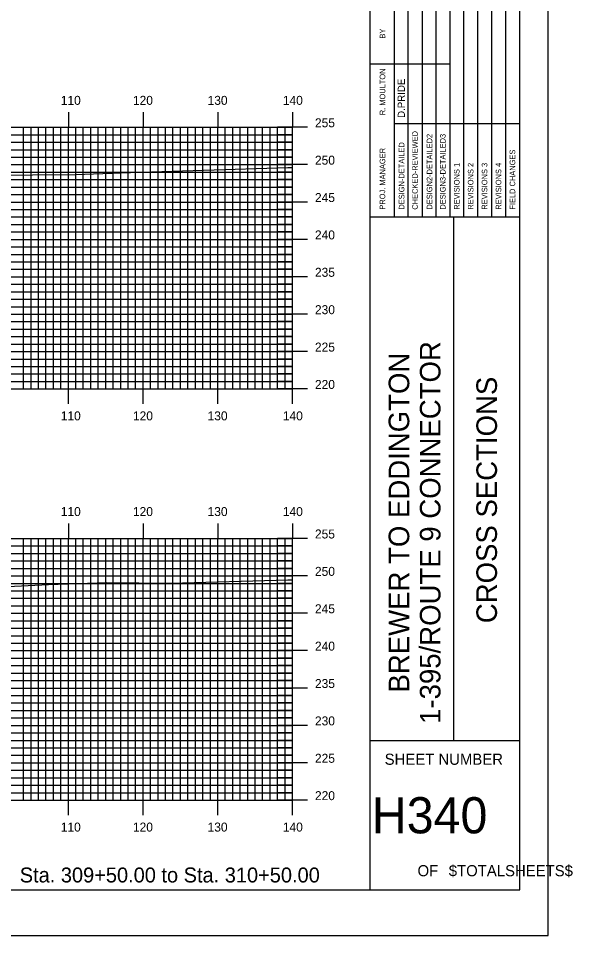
# Model space of a CAD drawing. Extents: x 1818063 to 1818407, y 442591 to 442811.
# Drawn here: x 1818332.4 to 1818406.6, y 442590.5 to 442713.2 of the extents above; entities that cross this region are included whole.
import ezdxf

# ---------------------------------------------------------------- set-up
doc = ezdxf.new("R2010")
doc.units = 0
for name, color, linetype in [('BORDER', 7, 'Continuous'), ('H_V ANNOTATION', 7, 'Continuous'), ('MAJOR', 7, 'Continuous'), ('MINOR', 7, 'Continuous'), ('PLOT BOUNDARY', 7, 'Continuous'), ('S_Roadway_Centerline', 7, 'Continuous')]:
    doc.layers.add(name, color=color, linetype=linetype)

msp = doc.modelspace()

# ---------------------------------------------------------------- linework, layer by layer
at = {"layer": 'BORDER'}
for p, q in [((1818379.53, 442596.67), (1818379.53, 442806.67)), ((1818379.53, 442686.67), (1818399.53, 442686.67)), ((1818390.71, 442616.67), (1818390.71, 442686.67)), ((1818379.53, 442616.67), (1818399.53, 442616.67))]:
    msp.add_line(p, q, dxfattribs=at)
msp.add_lwpolyline([(1818079.53, 442596.67), (1818399.53, 442596.67), (1818399.53, 442806.67), (1818079.53, 442806.67)], close=True, dxfattribs=at)
for points in [[(1818384.62, 442686.68), (1818384.62, 442721.67)], [(1818386.48, 442721.67), (1818386.48, 442686.68)], [(1818388.35, 442686.68), (1818388.35, 442721.67)], [(1818390.21, 442686.68), (1818390.21, 442721.67)], [(1818392.07, 442686.68), (1818392.07, 442721.67)], [(1818393.94, 442686.68), (1818393.94, 442721.67)], [(1818395.8, 442686.68), (1818395.8, 442721.67)], [(1818397.66, 442686.68), (1818397.66, 442721.67)], [(1818382.76, 442686.68), (1818382.76, 442720.26)], [(1818379.53, 442707.17), (1818382.76, 442707.17)], [(1818382.76, 442707.17), (1818390.21, 442707.17)], [(1818382.76, 442699.17), (1818399.53, 442699.17)]]:
    msp.add_lwpolyline(points, dxfattribs=at)
at = {"layer": 'MAJOR'}
for p, q in [((1818339.13, 442700.67), (1818339.13, 442698.67)), ((1818349.13, 442700.67), (1818349.13, 442698.67)), ((1818359.13, 442700.67), (1818359.13, 442698.67)), ((1818369.13, 442700.67), (1818369.13, 442698.67)), ((1818089.13, 442698.67), (1818369.13, 442698.67)), ((1818089.13, 442698.67), (1818369.13, 442698.67)), ((1818339.13, 442663.67), (1818339.13, 442698.67)), ((1818349.13, 442663.67), (1818349.13, 442698.67)), ((1818359.13, 442663.67), (1818359.13, 442698.67)), ((1818371.13, 442698.67), (1818367.12, 442698.67)), ((1818369.13, 442663.67), (1818369.13, 442698.67)), ((1818369.13, 442663.67), (1818369.13, 442698.67)), ((1818089.13, 442693.67), (1818369.13, 442693.67)), ((1818371.13, 442693.67), (1818367.12, 442693.67)), ((1818089.13, 442688.67), (1818369.13, 442688.67)), ((1818371.13, 442688.67), (1818367.12, 442688.67)), ((1818089.13, 442683.67), (1818369.13, 442683.67)), ((1818371.13, 442683.67), (1818367.12, 442683.67)), ((1818089.13, 442678.67), (1818369.13, 442678.67)), ((1818371.13, 442678.67), (1818367.12, 442678.67)), ((1818089.13, 442673.67), (1818369.13, 442673.67)), ((1818371.13, 442673.67), (1818367.12, 442673.67)), ((1818089.13, 442668.67), (1818369.13, 442668.67)), ((1818371.13, 442668.67), (1818367.12, 442668.67)), ((1818089.13, 442663.67), (1818369.13, 442663.67)), ((1818089.13, 442663.67), (1818369.13, 442663.67)), ((1818339.13, 442661.66), (1818339.13, 442663.67)), ((1818349.13, 442661.66), (1818349.13, 442663.67)), ((1818359.13, 442661.66), (1818359.13, 442663.67)), ((1818371.13, 442663.67), (1818367.12, 442663.67)), ((1818369.13, 442661.66), (1818369.13, 442663.67)), ((1818339.13, 442645.67), (1818339.13, 442643.67)), ((1818349.13, 442645.67), (1818349.13, 442643.67)), ((1818359.13, 442645.67), (1818359.13, 442643.67)), ((1818369.13, 442645.67), (1818369.13, 442643.67)), ((1818089.13, 442643.67), (1818369.13, 442643.67)), ((1818089.13, 442643.67), (1818369.13, 442643.67)), ((1818339.13, 442608.67), (1818339.13, 442643.67)), ((1818349.13, 442608.67), (1818349.13, 442643.67)), ((1818359.13, 442608.67), (1818359.13, 442643.67)), ((1818371.13, 442643.67), (1818367.12, 442643.67)), ((1818369.13, 442608.67), (1818369.13, 442643.67)), ((1818369.13, 442608.67), (1818369.13, 442643.67)), ((1818089.13, 442638.67), (1818369.13, 442638.67)), ((1818371.13, 442638.67), (1818367.12, 442638.67)), ((1818089.13, 442633.67), (1818369.13, 442633.67)), ((1818371.13, 442633.67), (1818367.12, 442633.67)), ((1818089.13, 442628.67), (1818369.13, 442628.67)), ((1818371.13, 442628.67), (1818367.12, 442628.67)), ((1818089.13, 442623.67), (1818369.13, 442623.67)), ((1818371.13, 442623.67), (1818367.12, 442623.67)), ((1818089.13, 442618.67), (1818369.13, 442618.67)), ((1818371.13, 442618.67), (1818367.12, 442618.67)), ((1818089.13, 442613.67), (1818369.13, 442613.67)), ((1818371.13, 442613.67), (1818367.12, 442613.67)), ((1818089.13, 442608.67), (1818369.13, 442608.67)), ((1818089.13, 442608.67), (1818369.13, 442608.67)), ((1818339.13, 442606.66), (1818339.13, 442608.67)), ((1818349.13, 442606.66), (1818349.13, 442608.67)), ((1818359.13, 442606.66), (1818359.13, 442608.67)), ((1818371.13, 442608.67), (1818367.12, 442608.67)), ((1818369.13, 442606.66), (1818369.13, 442608.67))]:
    msp.add_line(p, q, dxfattribs=at)
at = {"layer": 'MINOR'}
for p, q in [((1818333.13, 442663.67), (1818333.13, 442698.67)), ((1818334.13, 442663.67), (1818334.13, 442698.67)), ((1818335.13, 442663.67), (1818335.13, 442698.67)), ((1818336.13, 442663.67), (1818336.13, 442698.67)), ((1818337.13, 442663.67), (1818337.13, 442698.67)), ((1818338.13, 442663.67), (1818338.13, 442698.67)), ((1818340.13, 442663.67), (1818340.13, 442698.67)), ((1818341.13, 442663.67), (1818341.13, 442698.67)), ((1818342.13, 442663.67), (1818342.13, 442698.67)), ((1818343.13, 442663.67), (1818343.13, 442698.67)), ((1818344.13, 442663.67), (1818344.13, 442698.67)), ((1818345.13, 442663.67), (1818345.13, 442698.67)), ((1818346.13, 442663.67), (1818346.13, 442698.67)), ((1818347.13, 442663.67), (1818347.13, 442698.67)), ((1818348.13, 442663.67), (1818348.13, 442698.67)), ((1818350.13, 442663.67), (1818350.13, 442698.67)), ((1818351.13, 442663.67), (1818351.13, 442698.67)), ((1818352.13, 442663.67), (1818352.13, 442698.67)), ((1818353.13, 442663.67), (1818353.13, 442698.67)), ((1818354.13, 442663.67), (1818354.13, 442698.67)), ((1818355.13, 442663.67), (1818355.13, 442698.67)), ((1818356.13, 442663.67), (1818356.13, 442698.67)), ((1818357.13, 442663.67), (1818357.13, 442698.67)), ((1818358.13, 442663.67), (1818358.13, 442698.67)), ((1818360.13, 442663.67), (1818360.13, 442698.67)), ((1818361.13, 442663.67), (1818361.13, 442698.67)), ((1818362.13, 442663.67), (1818362.13, 442698.67)), ((1818363.13, 442663.67), (1818363.13, 442698.67)), ((1818364.13, 442663.67), (1818364.13, 442698.67)), ((1818365.13, 442663.67), (1818365.13, 442698.67)), ((1818366.13, 442663.67), (1818366.13, 442698.67)), ((1818367.13, 442663.67), (1818367.13, 442698.67)), ((1818368.13, 442663.67), (1818368.13, 442698.67)), ((1818089.13, 442697.67), (1818369.13, 442697.67)), ((1818089.13, 442696.67), (1818369.13, 442696.67)), ((1818369.13, 442697.67), (1818367.12, 442697.67)), ((1818369.13, 442696.67), (1818367.12, 442696.67)), ((1818089.13, 442695.67), (1818369.13, 442695.67)), ((1818369.13, 442695.67), (1818367.12, 442695.67)), ((1818089.13, 442694.67), (1818369.13, 442694.67)), ((1818369.13, 442694.67), (1818367.12, 442694.67)), ((1818089.13, 442692.67), (1818369.13, 442692.67)), ((1818369.13, 442692.67), (1818367.12, 442692.67)), ((1818089.13, 442691.67), (1818369.13, 442691.67)), ((1818089.13, 442690.67), (1818369.13, 442690.67)), ((1818369.13, 442691.67), (1818367.12, 442691.67)), ((1818369.13, 442690.67), (1818367.12, 442690.67)), ((1818089.13, 442689.67), (1818369.13, 442689.67)), ((1818369.13, 442689.67), (1818367.12, 442689.67)), ((1818089.13, 442687.67), (1818369.13, 442687.67)), ((1818369.13, 442687.67), (1818367.12, 442687.67)), ((1818089.13, 442686.67), (1818369.13, 442686.67)), ((1818089.13, 442685.67), (1818369.13, 442685.67)), ((1818369.13, 442686.67), (1818367.12, 442686.67)), ((1818369.13, 442685.67), (1818367.12, 442685.67)), ((1818089.13, 442684.67), (1818369.13, 442684.67)), ((1818369.13, 442684.67), (1818367.12, 442684.67)), ((1818089.13, 442682.67), (1818369.13, 442682.67)), ((1818369.13, 442682.67), (1818367.12, 442682.67)), ((1818089.13, 442681.67), (1818369.13, 442681.67)), ((1818089.13, 442680.67), (1818369.13, 442680.67)), ((1818369.13, 442681.67), (1818367.12, 442681.67)), ((1818369.13, 442680.67), (1818367.12, 442680.67)), ((1818089.13, 442679.67), (1818369.13, 442679.67)), ((1818369.13, 442679.67), (1818367.12, 442679.67)), ((1818089.13, 442677.67), (1818369.13, 442677.67)), ((1818369.13, 442677.67), (1818367.12, 442677.67)), ((1818089.13, 442676.67), (1818369.13, 442676.67)), ((1818369.13, 442676.67), (1818367.12, 442676.67)), ((1818089.13, 442675.67), (1818369.13, 442675.67)), ((1818089.13, 442674.67), (1818369.13, 442674.67)), ((1818369.13, 442675.67), (1818367.12, 442675.67)), ((1818369.13, 442674.67), (1818367.12, 442674.67)), ((1818089.13, 442672.67), (1818369.13, 442672.67)), ((1818369.13, 442672.67), (1818367.12, 442672.67)), ((1818089.13, 442671.67), (1818369.13, 442671.67)), ((1818369.13, 442671.67), (1818367.12, 442671.67)), ((1818089.13, 442670.67), (1818369.13, 442670.67)), ((1818089.13, 442669.67), (1818369.13, 442669.67)), ((1818369.13, 442670.67), (1818367.12, 442670.67)), ((1818369.13, 442669.67), (1818367.12, 442669.67)), ((1818089.13, 442667.67), (1818369.13, 442667.67)), ((1818369.13, 442667.67), (1818367.12, 442667.67)), ((1818089.13, 442666.67), (1818369.13, 442666.67)), ((1818369.13, 442666.67), (1818367.12, 442666.67)), ((1818089.13, 442665.67), (1818369.13, 442665.67)), ((1818369.13, 442665.67), (1818367.12, 442665.67)), ((1818089.13, 442664.67), (1818369.13, 442664.67)), ((1818369.13, 442664.67), (1818367.12, 442664.67)), ((1818089.13, 442642.67), (1818369.13, 442642.67)), ((1818333.13, 442608.67), (1818333.13, 442643.67)), ((1818334.13, 442608.67), (1818334.13, 442643.67)), ((1818335.13, 442608.67), (1818335.13, 442643.67)), ((1818336.13, 442608.67), (1818336.13, 442643.67)), ((1818337.13, 442608.67), (1818337.13, 442643.67)), ((1818338.13, 442608.67), (1818338.13, 442643.67)), ((1818340.13, 442608.67), (1818340.13, 442643.67)), ((1818341.13, 442608.67), (1818341.13, 442643.67)), ((1818342.13, 442608.67), (1818342.13, 442643.67)), ((1818343.13, 442608.67), (1818343.13, 442643.67)), ((1818344.13, 442608.67), (1818344.13, 442643.67)), ((1818345.13, 442608.67), (1818345.13, 442643.67)), ((1818346.13, 442608.67), (1818346.13, 442643.67)), ((1818347.13, 442608.67), (1818347.13, 442643.67)), ((1818348.13, 442608.67), (1818348.13, 442643.67)), ((1818350.13, 442608.67), (1818350.13, 442643.67)), ((1818351.13, 442608.67), (1818351.13, 442643.67)), ((1818352.13, 442608.67), (1818352.13, 442643.67)), ((1818353.13, 442608.67), (1818353.13, 442643.67)), ((1818354.13, 442608.67), (1818354.13, 442643.67)), ((1818355.13, 442608.67), (1818355.13, 442643.67)), ((1818356.13, 442608.67), (1818356.13, 442643.67)), ((1818357.13, 442608.67), (1818357.13, 442643.67)), ((1818358.13, 442608.67), (1818358.13, 442643.67)), ((1818360.13, 442608.67), (1818360.13, 442643.67)), ((1818361.13, 442608.67), (1818361.13, 442643.67)), ((1818362.13, 442608.67), (1818362.13, 442643.67)), ((1818363.13, 442608.67), (1818363.13, 442643.67)), ((1818364.13, 442608.67), (1818364.13, 442643.67)), ((1818365.13, 442608.67), (1818365.13, 442643.67)), ((1818366.13, 442608.67), (1818366.13, 442643.67)), ((1818369.13, 442642.67), (1818367.12, 442642.67)), ((1818367.13, 442608.67), (1818367.13, 442643.67)), ((1818368.13, 442608.67), (1818368.13, 442643.67)), ((1818089.13, 442641.67), (1818369.13, 442641.67)), ((1818369.13, 442641.67), (1818367.12, 442641.67)), ((1818089.13, 442640.67), (1818369.13, 442640.67)), ((1818369.13, 442640.67), (1818367.12, 442640.67)), ((1818089.13, 442639.67), (1818369.13, 442639.67)), ((1818369.13, 442639.67), (1818367.12, 442639.67)), ((1818089.13, 442637.67), (1818369.13, 442637.67)), ((1818089.13, 442636.67), (1818369.13, 442636.67)), ((1818369.13, 442637.67), (1818367.12, 442637.67)), ((1818369.13, 442636.67), (1818367.12, 442636.67)), ((1818089.13, 442635.67), (1818369.13, 442635.67)), ((1818369.13, 442635.67), (1818367.12, 442635.67)), ((1818089.13, 442634.67), (1818369.13, 442634.67)), ((1818369.13, 442634.67), (1818367.12, 442634.67)), ((1818089.13, 442632.67), (1818369.13, 442632.67)), ((1818089.13, 442631.67), (1818369.13, 442631.67)), ((1818369.13, 442632.67), (1818367.12, 442632.67)), ((1818369.13, 442631.67), (1818367.12, 442631.67)), ((1818089.13, 442630.67), (1818369.13, 442630.67)), ((1818369.13, 442630.67), (1818367.12, 442630.67)), ((1818089.13, 442629.67), (1818369.13, 442629.67)), ((1818369.13, 442629.67), (1818367.12, 442629.67)), ((1818089.13, 442627.67), (1818369.13, 442627.67)), ((1818089.13, 442626.67), (1818369.13, 442626.67)), ((1818369.13, 442627.67), (1818367.12, 442627.67)), ((1818369.13, 442626.67), (1818367.12, 442626.67)), ((1818089.13, 442625.67), (1818369.13, 442625.67)), ((1818369.13, 442625.67), (1818367.12, 442625.67)), ((1818089.13, 442624.67), (1818369.13, 442624.67)), ((1818369.13, 442624.67), (1818367.12, 442624.67)), ((1818089.13, 442622.67), (1818369.13, 442622.67)), ((1818369.13, 442622.67), (1818367.12, 442622.67)), ((1818089.13, 442621.67), (1818369.13, 442621.67)), ((1818089.13, 442620.67), (1818369.13, 442620.67)), ((1818369.13, 442621.67), (1818367.12, 442621.67)), ((1818369.13, 442620.67), (1818367.12, 442620.67)), ((1818089.13, 442619.67), (1818369.13, 442619.67)), ((1818369.13, 442619.67), (1818367.12, 442619.67)), ((1818089.13, 442617.67), (1818369.13, 442617.67)), ((1818369.13, 442617.67), (1818367.12, 442617.67)), ((1818089.13, 442616.67), (1818369.13, 442616.67)), ((1818089.13, 442615.67), (1818369.13, 442615.67)), ((1818369.13, 442616.67), (1818367.12, 442616.67)), ((1818369.13, 442615.67), (1818367.12, 442615.67)), ((1818089.13, 442614.67), (1818369.13, 442614.67)), ((1818369.13, 442614.67), (1818367.12, 442614.67)), ((1818089.13, 442612.67), (1818369.13, 442612.67)), ((1818369.13, 442612.67), (1818367.12, 442612.67)), ((1818089.13, 442611.67), (1818369.13, 442611.67)), ((1818369.13, 442611.67), (1818367.12, 442611.67)), ((1818089.13, 442610.67), (1818369.13, 442610.67)), ((1818089.13, 442609.67), (1818369.13, 442609.67)), ((1818369.13, 442610.67), (1818367.12, 442610.67)), ((1818369.13, 442609.67), (1818367.12, 442609.67))]:
    msp.add_line(p, q, dxfattribs=at)
at = {"layer": 'PLOT BOUNDARY'}
msp.add_lwpolyline([(1818063.34, 442590.55), (1818403.34, 442590.55), (1818403.34, 442810.55), (1818063.34, 442810.55)], close=True, dxfattribs=at)
at = {"layer": 'S_Roadway_Centerline'}
for points in [[(1818255.97, 442689.14), (1818265.92, 442689.77), (1818272.04, 442689.95), (1818279.28, 442689.96), (1818289.79, 442690.62), (1818293.13, 442690.84), (1818306.9, 442691.16), (1818321.08, 442692.02), (1818323.8, 442692.12), (1818328.59, 442692.26), (1818340.05, 442692.37), (1818347.43, 442692.61), (1818357.22, 442692.94), (1818368.5, 442693.27), (1818369.13, 442693.28)], [(1818254.12, 442634.29), (1818267.71, 442635.24), (1818277.04, 442635.55), (1818285.56, 442636.1), (1818290.76, 442636.35), (1818302.65, 442636.76), (1818310.29, 442637.08), (1818317.47, 442637.32), (1818319.29, 442637.36), (1818331.02, 442637.26), (1818336.48, 442637.5), (1818344.28, 442637.8), (1818352.85, 442637.69), (1818368.49, 442638.15), (1818369.13, 442638.16)]]:
    msp.add_lwpolyline(points, dxfattribs=at)

# ---------------------------------------------------------------- texts
at = {"layer": 'BORDER'}
for s, height, p in [('BY', 0.743, (1818381.53, 442710.54)), ('R. MOULTON', 0.745, (1818381.54, 442700.28)), ('D.PRIDE', 0.969, (1818384.17, 442699.92)), ('CHECKED-REVIEWED', 0.7455, (1818385.89, 442687.65)), ('DESIGN-DETAILED', 0.7455, (1818384.1, 442687.65)), ('DESIGN2-DETAILED2', 0.7455, (1818387.83, 442687.65)), ('DESIGN3-DETAILED3', 0.7455, (1818389.61, 442687.65)), ('PROJ. MANAGER', 0.7455, (1818381.53, 442687.65)), ('FIELD CHANGES', 0.7455, (1818398.93, 442687.65)), ('REVISIONS 1', 0.7455, (1818391.48, 442687.65)), ('REVISIONS 2', 0.7455, (1818393.34, 442687.65)), ('REVISIONS 3', 0.7455, (1818395.2, 442687.65)), ('REVISIONS 4', 0.7455, (1818397.07, 442687.65)), ('1-395/ROUTE 9 CONNECTOR', 2.7557, (1818388.93, 442618.87)), ('BREWER TO EDDINGTON', 2.7557, (1818384.75, 442623.07)), ('CROSS SECTIONS', 2.7557, (1818396.49, 442632.34))]:
    msp.add_text(s, height=height, rotation=90, dxfattribs=at).set_placement(p)
for s, height, p in [('SHEET NUMBER', 1.4905, (1818381.46, 442613.4)), ('H340', 4.839, (1818379.74, 442604.23)), ('OF', 1.491, (1818385.86, 442598.49)), ('$TOTALSHEETS$', 1.4905, (1818390.04, 442598.49))]:
    msp.add_text(s, height=height, dxfattribs=at).set_placement(p)
at = {"layer": 'H_V ANNOTATION'}
for s, height, p in [('110', 1.2, (1818338.11, 442701.67)), ('120', 1.2, (1818347.77, 442701.67)), ('130', 1.2, (1818357.76, 442701.67)), ('140', 1.2, (1818367.83, 442701.67)), ('255', 1.2, (1818372.13, 442698.67)), ('250', 1.2, (1818372.13, 442693.67)), ('245', 1.2, (1818372.13, 442688.67)), ('240', 1.2, (1818372.13, 442683.67)), ('235', 1.2, (1818372.13, 442678.67)), ('230', 1.2, (1818372.13, 442673.67)), ('225', 1.2, (1818372.13, 442668.67)), ('220', 1.2, (1818372.13, 442663.67)), ('110', 1.2, (1818338.11, 442659.47)), ('120', 1.2, (1818347.77, 442659.47)), ('130', 1.2, (1818357.76, 442659.47)), ('140', 1.2, (1818367.83, 442659.47)), ('110', 1.2, (1818338.11, 442646.67)), ('120', 1.2, (1818347.77, 442646.67)), ('130', 1.2, (1818357.76, 442646.67)), ('140', 1.2, (1818367.83, 442646.67)), ('255', 1.2, (1818372.13, 442643.67)), ('250', 1.2, (1818372.13, 442638.67)), ('245', 1.2, (1818372.13, 442633.67)), ('240', 1.2, (1818372.13, 442628.67)), ('235', 1.2, (1818372.13, 442623.67)), ('230', 1.2, (1818372.13, 442618.67)), ('225', 1.2, (1818372.13, 442613.67)), ('220', 1.2, (1818372.13, 442608.67)), ('110', 1.2, (1818338.11, 442604.47)), ('120', 1.2, (1818347.77, 442604.47)), ('130', 1.2, (1818357.76, 442604.47)), ('140', 1.2, (1818367.83, 442604.47)), ('Sta. 309+50.00 to Sta. 310+50.00', 2.0004, (1818332.62, 442597.66))]:
    msp.add_text(s, height=height, dxfattribs=at).set_placement(p)

doc.saveas('drawing.dxf')
